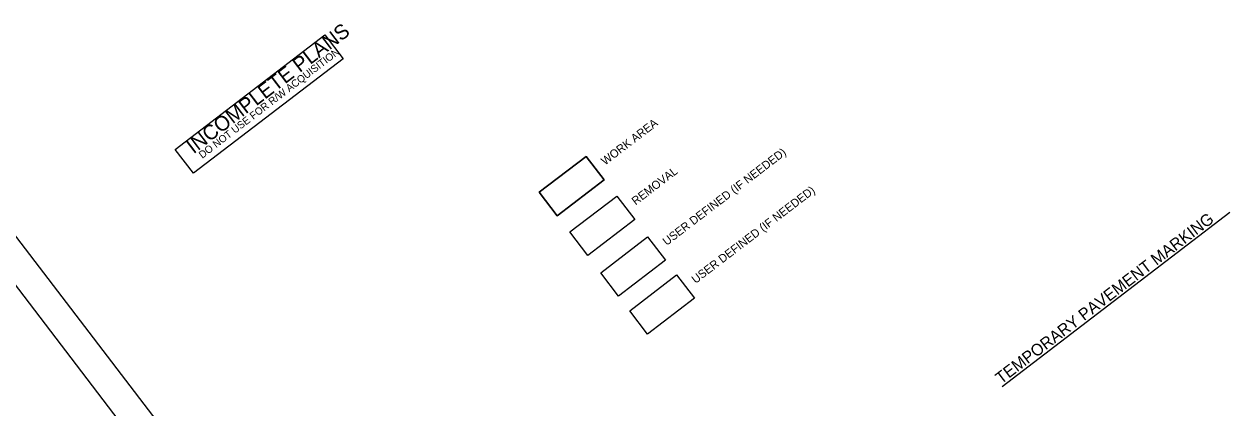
# Model space of a CAD drawing. Extents: x -606 to 2396, y -305 to 3662.
# Drawn here: x 1374 to 2396, y 1764 to 2090 of the extents above; entities that cross this region are included whole.
import ezdxf

# ---------------------------------------------------------------- set-up
doc = ezdxf.new("R2010")
doc.units = 0
for name, color, linetype in [('DEV BORDER CELL', 7, 'Continuous'), ('Gray Area Fill Shapes', 7, 'Continuous'), ('Sheet Plot Border Outside CELL', 7, 'Continuous'), ('Sheet Sticker Incomplete CELL', 7, 'Continuous')]:
    doc.layers.add(name, color=color, linetype=linetype)

msp = doc.modelspace()

# ---------------------------------------------------------------- linework, layer by layer
at = {"layer": 'DEV BORDER CELL'}
for p, q in [((2203.2, 1782.7), (2396.3, 1930.2)), ((1963.2, 1088.6), (1337.9, 1906.4))]:
    msp.add_line(p, q, dxfattribs=at)
for points in [[(1850.5, 1977.5), (1810.8, 1947.2), (1826, 1927.3), (1865.7, 1957.7)], [(1810.8, 1947.2), (1850.5, 1977.5), (1865.7, 1957.7), (1826, 1927.3)], [(1836.8, 1913.5), (1876.5, 1943.9), (1891.7, 1924), (1852, 1893.7)], [(1836.8, 1913.5), (1876.5, 1943.9), (1891.7, 1924), (1852, 1893.7)], [(1836.8, 1913.5), (1876.5, 1943.9), (1891.7, 1924), (1852, 1893.7)], [(1862.9, 1879), (1902.6, 1909.4), (1917.8, 1889.5), (1878.1, 1859.1)], [(1887.5, 1846.8), (1927.2, 1877.2), (1942.4, 1857.4), (1902.7, 1827)]]:
    msp.add_lwpolyline(points, close=True, dxfattribs=at)
at = {"layer": 'Gray Area Fill Shapes'}
msp.add_lwpolyline([(1826, 1927.3), (1865.7, 1957.7), (1850.5, 1977.5), (1810.8, 1947.2)], close=True, dxfattribs=at)
at = {"layer": 'Sheet Plot Border Outside CELL'}
msp.add_lwpolyline([(663.6, 50.4), (2004.5, 1075.8), (1336.4, 1949.6), (-4.5, 924.2)], close=True, dxfattribs=at)
at = {"layer": 'Sheet Sticker Incomplete CELL'}
msp.add_lwpolyline([(1517.7, 1963.2), (1502.2, 1983.5), (1629, 2080.5), (1644.5, 2060.2)], close=True, dxfattribs=at)

# ---------------------------------------------------------------- texts
at = {"layer": 'DEV BORDER CELL'}
for s, height, rotation, p in [('WORK AREA', 7, 37.404, (1866.6, 1969.7)), ('USER DEFINED (IF NEEDED)', 7, 37.404, (1918.8, 1901.6)), ('REMOVAL', 7, 37.404, (1892.5, 1935.9)), ('USER DEFINED (IF NEEDED)', 7, 37.404, (1943.3, 1869.4)), ('TEMPORARY PAVEMENT MARKING ', 10, 37.3638, (2202.4, 1784.2))]:
    msp.add_text(s, height=height, rotation=rotation, dxfattribs=at).set_placement(p)
at = {"layer": 'Sheet Sticker Incomplete CELL'}
for s, height, p in [('INCOMPLETE PLANS', 12.509, (1517.7, 1979.2)), ('DO NOT USE FOR R/W ACQUISITION', 6.255, (1525.1, 1975.4))]:
    msp.add_text(s, height=height, rotation=37.404, dxfattribs=at).set_placement(p)

doc.saveas('drawing.dxf')
